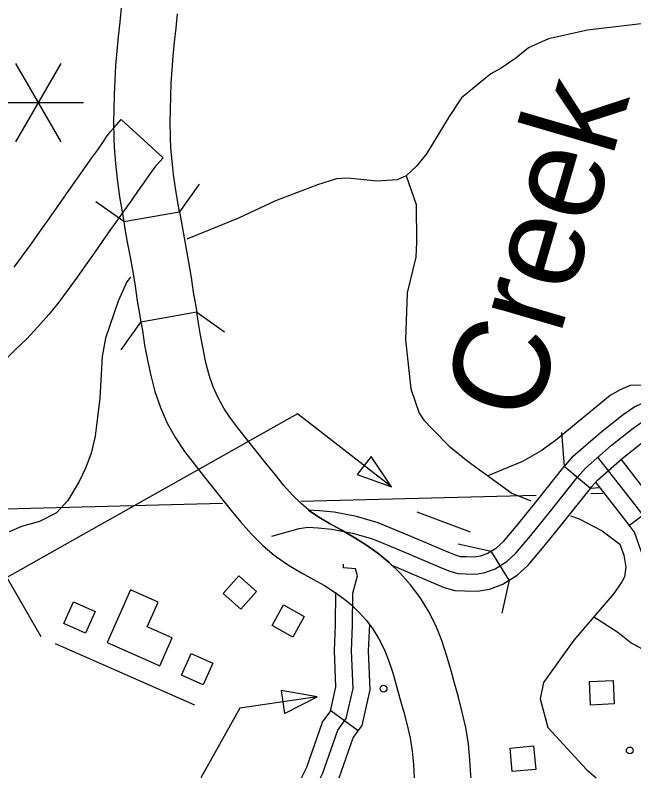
# Model space of a CAD drawing. Extents: x 1370130 to 1380143, y 377636 to 380256.
# Drawn here: x 1377470.1 to 1377546.5, y 378830.6 to 378924.8 of the extents above; entities that cross this region are included whole.
import ezdxf

# ---------------------------------------------------------------- set-up
doc = ezdxf.new("R2010")
doc.units = 0
for name, color, linetype in [('Level 10', 7, 'Continuous'), ('Level 31', 7, 'Continuous'), ('Level 32', 7, 'Continuous'), ('Level 35', 7, 'Continuous'), ('Level 37', 7, 'Continuous'), ('Level 38', 7, 'Continuous'), ('Level 48', 7, 'Continuous'), ('Level 5', 7, 'Continuous'), ('Level 56', 7, 'Continuous'), ('Level 57', 7, 'Continuous'), ('Level 58', 7, 'Continuous'), ('Level 6', 7, 'Continuous')]:
    doc.layers.add(name, color=color, linetype=linetype)

msp = doc.modelspace()

# ---------------------------------------------------------------- linework, layer by layer
at = {"layer": 'Level 10'}
for p, q in [((1377483.191, 378911.899), (1377488.342, 378907.16)), ((1377483.483, 378899.315), (1377490.384, 378900.487)), ((1377492.506, 378888.088), (1377485.609, 378886.892)), ((1377506.305, 378863.663), (1377506.609, 378863.431)), ((1377502.065, 378858.106), (1377502.37, 378857.874))]:
    msp.add_line(p, q, dxfattribs=at)
for points in [[(1377483.184, 378925.695), (1377482.997, 378923.913), (1377482.811, 378922.133), (1377482.64, 378920.349), (1377482.487, 378918.55), (1377482.371, 378916.745), (1377482.293, 378914.963), (1377482.25, 378913.212), (1377482.234, 378911.471), (1377482.254, 378909.701), (1377482.271, 378909.362)], [(1377489.263, 378909.697), (1377489.252, 378909.909), (1377489.234, 378911.478), (1377489.25, 378913.093), (1377489.289, 378914.726), (1377489.361, 378916.368), (1377489.468, 378918.029), (1377489.611, 378919.718), (1377489.776, 378921.436), (1377489.958, 378923.184), (1377490.145, 378924.954)], [(1377469.944, 378893.655), (1377471, 378895.055), (1377472.039, 378896.511), (1377473.093, 378897.994), (1377474.117, 378899.43), (1377475.094, 378900.829), (1377476.046, 378902.186), (1377476.98, 378903.527), (1377477.903, 378904.826), (1377478.762, 378906.036), (1377479.56, 378907.164), (1377480.277, 378908.172), (1377480.898, 378909.076), (1377481.462, 378909.865), (1377481.905, 378910.445), (1377482.248, 378910.875), (1377483.191, 378911.899)], [(1377482.271, 378909.362), (1377482.341, 378907.895), (1377482.494, 378906.066), (1377482.71, 378904.212), (1377482.979, 378902.346), (1377483.284, 378900.488), (1377483.483, 378899.315)], [(1377490.384, 378900.487), (1377490.188, 378901.641), (1377489.897, 378903.412), (1377489.652, 378905.115), (1377489.46, 378906.764), (1377489.327, 378908.355), (1377489.263, 378909.697)], [(1377488.342, 378907.16), (1377487.564, 378906.314), (1377487.422, 378906.137), (1377487.093, 378905.705), (1377486.63, 378905.057), (1377486.014, 378904.162), (1377485.269, 378903.114), (1377484.474, 378901.989), (1377483.61, 378900.772), (1377482.705, 378899.499), (1377481.784, 378898.176), (1377480.829, 378896.815), (1377479.836, 378895.394), (1377478.796, 378893.934), (1377477.74, 378892.449), (1377476.644, 378890.914), (1377475.466, 378889.352), (1377474.219, 378887.802), (1377472.896, 378886.284), (1377471.51, 378884.82), (1377470.1, 378883.436), (1377468.702, 378882.102)], [(1377490.384, 378900.487), (1377490.497, 378899.822), (1377490.819, 378897.997), (1377491.159, 378896.15), (1377491.499, 378894.276), (1377491.811, 378892.392), (1377492.079, 378890.594), (1377492.379, 378888.822), (1377492.506, 378888.088)], [(1377483.483, 378899.315), (1377483.599, 378898.628), (1377483.93, 378896.755), (1377484.273, 378894.89), (1377484.602, 378893.078), (1377484.896, 378891.306), (1377485.165, 378889.494), (1377485.48, 378887.639), (1377485.609, 378886.892)], [(1377506.609, 378863.431), (1377505.43, 378864.437), (1377504.348, 378865.51), (1377503.285, 378866.712), (1377502.185, 378868.049), (1377501.051, 378869.444), (1377499.928, 378870.853), (1377498.812, 378872.267), (1377497.718, 378873.658), (1377496.687, 378874.999), (1377495.852, 378876.247), (1377495.138, 378877.534), (1377494.539, 378878.885), (1377494.052, 378880.325), (1377493.651, 378881.879), (1377493.306, 378883.562), (1377492.967, 378885.274), (1377492.694, 378887.006), (1377492.506, 378888.088)], [(1377485.609, 378886.892), (1377485.788, 378885.862), (1377486.074, 378884.048), (1377486.444, 378882.179), (1377486.829, 378880.302), (1377487.338, 378878.327), (1377488.011, 378876.338), (1377488.865, 378874.411), (1377489.872, 378872.596), (1377490.998, 378870.915), (1377492.192, 378869.362), (1377493.313, 378867.936), (1377494.444, 378866.503), (1377495.597, 378865.055), (1377496.766, 378863.617), (1377497.96, 378862.166), (1377499.257, 378860.7), (1377500.687, 378859.283), (1377502.065, 378858.106)], [(1377526.398, 378830.61), (1377526.369, 378830.929), (1377526.245, 378832.788), (1377526.057, 378834.778), (1377525.735, 378836.798), (1377525.31, 378838.729), (1377524.836, 378840.544), (1377524.358, 378842.273), (1377523.883, 378843.991), (1377523.376, 378845.757), (1377522.772, 378847.579), (1377522.025, 378849.404), (1377521.128, 378851.177), (1377520.085, 378852.866), (1377518.906, 378854.451), (1377517.624, 378855.888), (1377516.28, 378857.183), (1377514.858, 378858.363), (1377513.37, 378859.412), (1377511.849, 378860.362), (1377510.334, 378861.214), (1377508.919, 378861.998), (1377507.6, 378862.783), (1377506.305, 378863.663)], [(1377502.37, 378857.874), (1377503.84, 378856.875), (1377505.431, 378855.928), (1377506.922, 378855.102), (1377508.277, 378854.34), (1377509.497, 378853.578), (1377510.6, 378852.8), (1377511.611, 378851.962), (1377512.577, 378851.031), (1377513.476, 378850.024), (1377514.288, 378848.932), (1377515.015, 378847.753), (1377515.653, 378846.492), (1377516.203, 378845.149), (1377516.686, 378843.69), (1377517.145, 378842.091), (1377517.612, 378840.407), (1377518.076, 378838.727), (1377518.503, 378837.091), (1377518.854, 378835.495), (1377519.109, 378833.897), (1377519.267, 378832.226), (1377519.374, 378830.61)]]:
    msp.add_lwpolyline(points, dxfattribs=at)
at = {"layer": 'Level 31'}
msp.add_line((1377531.11, 378855.03), (1377528.874, 378858.585), dxfattribs=at)
for points in [[(1377538.095, 378869.259), (1377539.03, 378870.345), (1377542.368, 378873.261), (1377545.178, 378875.486), (1377546.624, 378876.45), (1377548.933, 378877.428), (1377550.909, 378878.194)], [(1377501.783, 378860.461), (1377505.141, 378861.393), (1377506.23, 378861.554), (1377507.521, 378861.474), (1377509.175, 378861.312), (1377511.757, 378860.828), (1377514.218, 378860.101), (1377517.204, 378858.89), (1377522.812, 378856.508), (1377523.78, 378856.105), (1377524.749, 378855.822), (1377525.717, 378855.782), (1377527.008, 378855.741), (1377528.097, 378855.943), (1377529.388, 378856.428), (1377530.801, 378857.316), (1377531.93, 378858.325), (1377533.786, 378860.545), (1377536.045, 378863.331), (1377539.515, 378867.69), (1377540.524, 378868.861), (1377543.711, 378871.647), (1377546.414, 378873.786), (1377547.625, 378874.593)], [(1377541.277, 378866.518), (1377542.018, 378867.378), (1377545.055, 378870.032), (1377547.651, 378872.086), (1377548.625, 378872.737), (1377550.512, 378873.535), (1377552.428, 378874.279)], [(1377528.874, 378858.585), (1377529.533, 378859), (1377530.417, 378859.789), (1377532.165, 378861.88), (1377534.408, 378864.646), (1377537.898, 378869.03), (1377538.095, 378869.259)], [(1377541.133, 378866.351), (1377537.898, 378869.03)], [(1377531.11, 378855.03), (1377532.068, 378855.632), (1377533.443, 378856.861), (1377535.407, 378859.21), (1377537.683, 378862.015), (1377541.133, 378866.351), (1377541.277, 378866.518)], [(1377516.907, 378861.277), (1377514.912, 378862.086), (1377512.249, 378862.872), (1377509.471, 378863.393), (1377507.689, 378863.567), (1377506.32, 378863.653), (1377507.6, 378862.783), (1377508.919, 378861.998), (1377510.334, 378861.214), (1377511.849, 378860.362), (1377513.37, 378859.412), (1377514.858, 378858.363), (1377516.28, 378857.183), (1377516.618, 378856.857)], [(1377528.874, 378858.585), (1377528.451, 378858.319), (1377527.533, 378857.974), (1377526.848, 378857.848), (1377525.794, 378857.88), (1377525.092, 378857.91), (1377524.481, 378858.088), (1377523.627, 378858.444), (1377518.009, 378860.83), (1377516.907, 378861.277)], [(1377516.618, 378856.857), (1377521.998, 378854.573), (1377523.08, 378854.122), (1377524.406, 378853.735), (1377525.64, 378853.683), (1377527.168, 378853.635), (1377528.662, 378853.912), (1377530.326, 378854.537), (1377531.11, 378855.03)]]:
    msp.add_lwpolyline(points, dxfattribs=at)
at = {"layer": 'Level 32'}
for p, q in [((1377549.304, 378864.297), (1377545.943, 378861.778)), ((1377512.449, 378836.39), (1377509.052, 378838.86))]:
    msp.add_line(p, q, dxfattribs=at)
for points in [[(1377564.416, 378830.61), (1377561.398, 378831.616), (1377558.243, 378832.466), (1377556.665, 378833.134), (1377554.905, 378834.652), (1377553.146, 378836.534), (1377551.386, 378838.962), (1377550.597, 378840.905), (1377550.354, 378842.544), (1377550.354, 378845.216), (1377550.476, 378847.341), (1377550.901, 378851.105), (1377551.083, 378852.744), (1377551.083, 378854.079), (1377550.84, 378855.597), (1377550.476, 378856.872), (1377550.175, 378858.028), (1377549.326, 378859.485), (1377548.435, 378861.955), (1377546.942, 378863.947), (1377542.066, 378870.209)], [(1377549.304, 378864.297), (1377548.611, 378865.222), (1377544.942, 378869.934)], [(1377545.943, 378861.778), (1377545.273, 378862.672), (1377541.803, 378867.129)], [(1377548.581, 378849.276), (1377548.814, 378851.338), (1377548.983, 378852.86), (1377548.983, 378853.913), (1377548.786, 378855.142), (1377548.45, 378856.319), (1377548.216, 378857.219), (1377547.415, 378858.592), (1377546.566, 378860.947), (1377545.943, 378861.778)], [(1377507.807, 378830.61), (1377508.045, 378831.087), (1377509.935, 378836.503), (1377510.979, 378837.939), (1377511.814, 378841.647), (1377511.631, 378846.29), (1377511.761, 378849.422), (1377511.802, 378853.402), (1377512.358, 378855.554), (1377512.118, 378856.394), (1377510.623, 378856.522), (1377510.623, 378857.001)], [(1377509.025, 378838.823), (1377509.705, 378841.84), (1377509.529, 378846.292), (1377509.662, 378849.476), (1377509.703, 378853.544)], [(1377512.449, 378836.39), (1377512.932, 378837.054), (1377513.923, 378841.455), (1377513.732, 378846.288), (1377513.87, 378849.582)], [(1377505.477, 378830.61), (1377505.491, 378830.675), (1377506.106, 378831.906), (1377508.055, 378837.487), (1377509.052, 378838.86)], [(1377510.103, 378830.61), (1377511.816, 378835.519), (1377512.449, 378836.39)]]:
    msp.add_lwpolyline(points, dxfattribs=at)
at = {"layer": 'Level 35'}
for points in [[(1377556.476, 378929.418), (1377555.325, 378927.963), (1377553.776, 378926.78), (1377550.644, 378924.666), (1377549.142, 378923.932), (1377540.762, 378922.943), (1377535.952, 378921.86), (1377533.474, 378920.769), (1377531.927, 378919.474), (1377530.126, 378918.23), (1377528.848, 378917.529), (1377525.228, 378914.563), (1377523.701, 378912.286), (1377520.902, 378907.653), (1377519.64, 378906.14), (1377518.373, 378904.934), (1377517.259, 378904.434), (1377514.79, 378904.27), (1377511.13, 378904.67), (1377509.783, 378904.558), (1377507.438, 378903.835), (1377502.225, 378901.845), (1377497.661, 378899.729), (1377491.273, 378897.142)], [(1377518.373, 378904.934), (1377519.596, 378901.396), (1377519.662, 378896.767), (1377519.588, 378894.886), (1377518.497, 378890.513), (1377518.279, 378884.672), (1377518.964, 378878.625), (1377519.98, 378875.644), (1377520.56, 378874.758), (1377521.622, 378873.658), (1377523.678, 378871.541), (1377526.042, 378869.673), (1377531.407, 378865.744), (1377533.776, 378864.815)], [(1377484.344, 378892.423), (1377483.858, 378891.863), (1377482.811, 378889.484), (1377481.219, 378884.876), (1377480.843, 378882.651), (1377480.527, 378877.481), (1377479.948, 378872.783), (1377479.457, 378870.696), (1377478.79, 378868.914), (1377477.983, 378867.186), (1377476.597, 378864.855), (1377475.196, 378863.339), (1377473.082, 378862.256), (1377470.847, 378861.648), (1377469.344, 378860.971)], [(1377551.776, 378878.559), (1377550.153, 378879.111), (1377546.05, 378879.036), (1377544.818, 378878.52), (1377543.559, 378877.802), (1377536.802, 378872.246), (1377535.053, 378870.976), (1377532.744, 378869.654), (1377528.455, 378867.906)], [(1377538.665, 378862.968), (1377539.727, 378862.577), (1377542.588, 378861.083), (1377544.752, 378859.439), (1377545.256, 378858.103), (1377545.511, 378856.621), (1377545.339, 378855.439), (1377545.014, 378854.814), (1377544.032, 378853.363), (1377539.065, 378847.59), (1377535.35, 378842.377), (1377534.913, 378840.375), (1377535.884, 378836.832), (1377540.683, 378831.573), (1377541.836, 378830.61)], [(1377541.506, 378850.503), (1377544.523, 378848.602), (1377546.179, 378847.262), (1377547.893, 378846.317)]]:
    msp.add_lwpolyline(points, dxfattribs=at)
at = {"layer": 'Level 37'}
for points in [[(1377492.814, 378903.912), (1377490.384, 378900.487)], [(1377483.483, 378899.315), (1377480.058, 378901.745)], [(1377492.506, 378888.088), (1377495.94, 378885.669)], [(1377483.19, 378883.458), (1377485.609, 378886.892)]]:
    msp.add_lwpolyline(points, dxfattribs=at)
at = {"layer": 'Level 38'}
for points in [[(1377537.917, 378869.053), (1377537.584, 378873.24)], [(1377542.35, 378866.427), (1377541.113, 378866.328)], [(1377524.779, 378859.518), (1377528.874, 378858.585)], [(1377531.11, 378855.03), (1377530.177, 378850.935)]]:
    msp.add_lwpolyline(points, dxfattribs=at)
at = {"layer": 'Level 48'}
for p, q in [((1377475.716, 378918.831), (1377470.116, 378909.132)), ((1377470.116, 378918.831), (1377475.716, 378909.132)), ((1377467.316, 378913.981), (1377478.516, 378913.981))]:
    msp.add_line(p, q, dxfattribs=at)
at = {"layer": 'Level 5'}
msp.add_lwpolyline([(1377542.666, 378865.723), (1377541.171, 378865.685)], dxfattribs=at)
at = {"layer": 'Level 56'}
for points in [[(1377516.573, 378866.548), (1377504.954, 378875.554), (1377469.071, 378855.326), (1377473.249, 378848.064)], [(1377519.688, 378863.468), (1377526.286, 378860.974)], [(1377475.009, 378847.184), (1377492.225, 378839.621)], [(1377507.373, 378840.583), (1377497.828, 378839.2), (1377493.028, 378830.61)]]:
    msp.add_lwpolyline(points, dxfattribs=at)
for points in [[(1377514.062, 378870.301), (1377512.312, 378868.044), (1377516.573, 378866.548)], [(1377495.754, 378853.378), (1377497.688, 378855.558), (1377499.875, 378853.618), (1377497.941, 378851.438)], [(1377476.093, 378849.654), (1377477.266, 378852.322), (1377479.942, 378851.146), (1377478.77, 378848.478)], [(1377501.808, 378849.409), (1377503.228, 378851.954), (1377505.78, 378850.529), (1377504.36, 378847.985)], [(1377490.634, 378843.266), (1377491.806, 378845.934), (1377494.482, 378844.759), (1377493.31, 378842.091)], [(1377541.161, 378839.59), (1377541.025, 378842.501), (1377543.945, 378842.637), (1377544.081, 378839.726)], [(1377531.466, 378831.38), (1377531.209, 378834.283), (1377534.12, 378834.541), (1377534.378, 378831.638)]]:
    msp.add_lwpolyline(points, close=True, dxfattribs=at)
msp.add_circle((1377515.583, 378841.61), 0.42, dxfattribs=at)
at = {"layer": 'Level 57'}
msp.add_lwpolyline([(1377502.929, 378841.382), (1377503.338, 378838.555), (1377507.373, 378840.583)], close=True, dxfattribs=at)
msp.add_circle((1377545.992, 378833.983), 0.42, dxfattribs=at)
at = {"layer": 'Level 58'}
msp.add_lwpolyline([(1377481.446, 378847.302), (1377487.958, 378844.442), (1377489.467, 378847.877), (1377486.386, 378849.231), (1377487.737, 378852.307), (1377484.306, 378853.814)], close=True, dxfattribs=at)
at = {"layer": 'Level 6'}
for points in [[(1377505.371, 378864.757), (1377534.426, 378865.51)], [(1377445.117, 378863.195), (1377495.673, 378864.505)]]:
    msp.add_lwpolyline(points, dxfattribs=at)

# ---------------------------------------------------------------- texts
at = {"layer": 'Level 35'}
msp.add_text('Creek', height=11.8272, rotation=73.6757, dxfattribs=at).set_placement((1377534.158, 378874.148))

doc.saveas('drawing.dxf')
